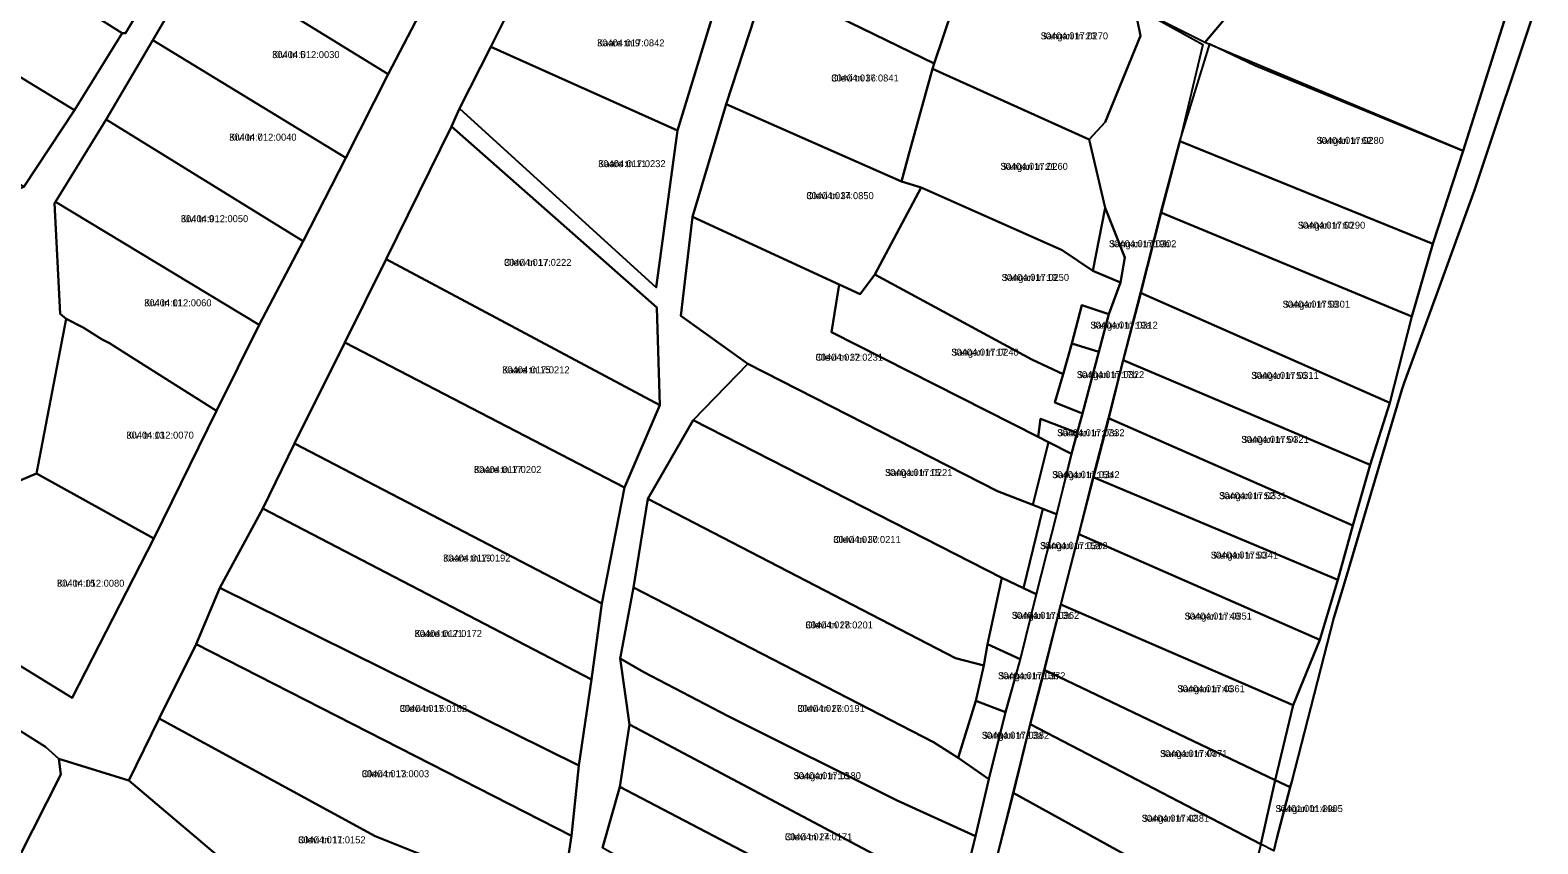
# Model space of a CAD drawing. Extents: x 542681 to 554572, y 6566489 to 6580482.
# Drawn here: x 544141.3 to 544465.9, y 6575987.4 to 6576162.5 of the extents above; entities that cross this region are included whole.
import ezdxf

# ---------------------------------------------------------------- set-up
doc = ezdxf.new("R2010")
doc.units = 0
for name, color, linetype in [('L_AADRESS', 7, 'Continuous'), ('PIIR', 7, 'Continuous'), ('TUNNUS', 7, 'Continuous')]:
    doc.layers.add(name, color=color, linetype=linetype)

msp = doc.modelspace()

# ---------------------------------------------------------------- linework, layer by layer
at = {"layer": 'PIIR'}
for points in [[(544421, 6576191.6), (544394.2, 6576159.83), (544381.29, 6576166.31), (544369.53, 6576171.4), (544386.58, 6576207.68)], [(544128.15, 6576198.87), (544130.62, 6576202.67), (544172.2, 6576179.15), (544161.88, 6576161.84), (544161.1, 6576161.82), (544120.28, 6576187.57)], [(544299.73, 6576172.96), (544295.43, 6576175.19), (544300.42, 6576176.92), (544309.48, 6576196.57), (544344.06, 6576179.43), (544335.91, 6576155.29)], [(544188.39, 6576194.26), (544189.79, 6576193.88), (544227.68, 6576170.79), (544218.42, 6576152.97), (544177.97, 6576177.9)], [(544434.83, 6576185.24), (544442.01, 6576193.33), (544442.75, 6576189.94), (544463.43, 6576179.69), (544449.82, 6576136.52), (544394.2, 6576159.83), (544421, 6576191.6)], [(544115.93, 6576181.35), (544120.28, 6576187.57), (544161.1, 6576161.82), (544150.9, 6576145.26), (544108.81, 6576170.96)], [(544344.06, 6576179.43), (544344.75, 6576182.07), (544375.81, 6576167.47), (544379.6, 6576164.76), (544380.36, 6576161.26), (544372.71, 6576142.68), (544369.28, 6576138.91), (544335.58, 6576154.14), (544335.91, 6576155.29)], [(544177.97, 6576177.9), (544218.42, 6576152.97), (544209.29, 6576135.03), (544167.75, 6576160.33)], [(544240.49, 6576158.91), (544248.48, 6576174.91), (544291.75, 6576177.06), (544280.65, 6576140.9)], [(544335.58, 6576154.14), (544330.6, 6576136.26), (544328.89, 6576129.9), (544291.15, 6576146.53), (544299.73, 6576172.96), (544335.91, 6576155.29)], [(544103.91, 6576164.12), (544108.81, 6576170.96), (544150.9, 6576145.26), (544139.99, 6576128.75), (544097.55, 6576154.68)], [(544167.75, 6576160.33), (544209.29, 6576135.03), (544200.13, 6576117.06), (544157.66, 6576143.26)], [(544388.78, 6576138.59), (544395.23, 6576159.52), (544405.01, 6576154.9), (544449.82, 6576136.52), (544443.25, 6576116.48)], [(544240.49, 6576158.91), (544280.65, 6576140.9), (544276.06, 6576107.08), (544233.74, 6576145.65)], [(544328.89, 6576129.9), (544330.6, 6576136.26), (544335.58, 6576154.14), (544369.28, 6576138.91), (544372.76, 6576124.24), (544370.08, 6576110.68), (544363.45, 6576115.13), (544333.09, 6576128.58)], [(544291.15, 6576146.53), (544328.89, 6576129.9), (544333.09, 6576128.58), (544323.16, 6576109.86), (544320.02, 6576105.69), (544315.45, 6576107.76), (544283.92, 6576122.33)], [(544157.66, 6576143.26), (544200.13, 6576117.06), (544190.66, 6576099.04), (544146.79, 6576125.53)], [(544232.03, 6576141.72), (544276.23, 6576102.8), (544276.88, 6576081.78), (544217.94, 6576113.17)], [(544384.73, 6576123.22), (544388.78, 6576138.59), (544443.25, 6576116.48), (544438.77, 6576100.88)], [(544333.09, 6576128.58), (544363.45, 6576115.13), (544370.08, 6576110.68), (544376.05, 6576108.18), (544373.54, 6576101.37), (544367.71, 6576103.28), (544365.56, 6576095.06), (544363.7, 6576088.45), (544356.92, 6576091.58), (544323.16, 6576109.86)], [(544146.54, 6576125.22), (544146.79, 6576125.53), (544190.66, 6576099.04), (544181.42, 6576080.58), (544165.84, 6576090.36), (544158.38, 6576095.09), (544156.84, 6576095.9), (544152.73, 6576098.48), (544149.06, 6576100.33), (544147.81, 6576101.4)], [(544376.99, 6576113.58), (544376.05, 6576108.18), (544370.08, 6576110.68), (544372.76, 6576124.24)], [(544281.41, 6576100.98), (544283.92, 6576122.33), (544315.45, 6576107.76), (544313.84, 6576097.48), (544358.27, 6576074.96), (544360.55, 6576073.83), (544357.13, 6576060.34), (544349.57, 6576063.23), (544295.78, 6576090.65)], [(544380.33, 6576105.93), (544384.73, 6576123.22), (544438.77, 6576100.88), (544434.03, 6576082.25)], [(544217.94, 6576113.17), (544276.88, 6576081.78), (544269.25, 6576064.08), (544209.08, 6576095.23)], [(544315.45, 6576107.76), (544320.02, 6576105.69), (544323.16, 6576109.86), (544356.92, 6576091.58), (544363.7, 6576088.45), (544361.89, 6576082.37), (544367.82, 6576079.98), (544366.71, 6576075.84), (544358.83, 6576078.86), (544358.27, 6576074.96), (544313.84, 6576097.48)], [(544376.58, 6576091.45), (544380.33, 6576105.93), (544434.03, 6576082.25), (544429.78, 6576068.92)], [(544367.71, 6576103.28), (544373.54, 6576101.37), (544371.36, 6576093.22), (544365.56, 6576095.06)], [(544149.06, 6576100.33), (544152.73, 6576098.48), (544156.84, 6576095.9), (544158.38, 6576095.09), (544165.84, 6576090.36), (544181.42, 6576080.58), (544167.98, 6576053.1), (544142.67, 6576067.09)], [(544209.08, 6576095.23), (544269.25, 6576064.08), (544264.4, 6576039.1), (544198.26, 6576073.49)], [(544363.7, 6576088.45), (544365.56, 6576095.06), (544371.36, 6576093.22), (544367.82, 6576079.98), (544361.89, 6576082.37)], [(544373.44, 6576078.94), (544376.58, 6576091.45), (544429.78, 6576068.92), (544426.05, 6576055.86)], [(544295.78, 6576090.65), (544349.57, 6576063.23), (544357.13, 6576060.34), (544359.28, 6576059.48), (544355.18, 6576042.4), (544350.48, 6576044.64), (544284.03, 6576078.54)], [(544284.03, 6576078.54), (544350.48, 6576044.64), (544347.38, 6576030.33), (544346.61, 6576025.71), (544340.53, 6576027.33), (544274.31, 6576061.6)], [(544358.27, 6576074.96), (544358.83, 6576078.86), (544366.71, 6576075.84), (544365.51, 6576071.33), (544360.55, 6576073.83)], [(544370.16, 6576066.26), (544373.44, 6576078.94), (544426.05, 6576055.86), (544422.84, 6576044.15)], [(544198.26, 6576073.49), (544264.4, 6576039.1), (544262.15, 6576022.75), (544191.4, 6576059.54)], [(544357.13, 6576060.34), (544360.55, 6576073.83), (544365.51, 6576071.33), (544362.26, 6576058.32), (544359.28, 6576059.48)], [(544136.1, 6576064.24), (544142.67, 6576067.09), (544167.98, 6576053.1), (544150.34, 6576018.8), (544126.25, 6576033.56)], [(544367.04, 6576054.02), (544370.16, 6576066.26), (544422.84, 6576044.15), (544418.91, 6576031.24)], [(544191.4, 6576059.54), (544262.15, 6576022.75), (544259.46, 6576004.22), (544182.18, 6576042.45)], [(544274.31, 6576061.6), (544340.53, 6576027.33), (544346.61, 6576025.71), (544344.9, 6576018.12), (544341.09, 6576005.84), (544335.74, 6576009.24), (544271.21, 6576042.52)], [(544355.18, 6576042.4), (544359.28, 6576059.48), (544362.26, 6576058.32), (544357.88, 6576041.11)], [(544363.16, 6576038.9), (544367.04, 6576054.02), (544418.91, 6576031.24), (544413.21, 6576017.24)], [(544259.46, 6576004.22), (544257.89, 6575989.06), (544177.07, 6576030.33), (544182.18, 6576042.45)], [(544273.43, 6576024.32), (544268.31, 6576027.25), (544271.21, 6576042.52), (544335.74, 6576009.24), (544341.09, 6576005.84), (544347.66, 6576001.27), (544344.79, 6575988.99), (544327.96, 6575996.68), (544291.56, 6576014.86)], [(544347.38, 6576030.33), (544350.48, 6576044.64), (544355.18, 6576042.4), (544357.88, 6576041.11), (544354.44, 6576027.12)], [(544359.63, 6576024.8), (544363.16, 6576038.9), (544413.21, 6576017.24), (544409.31, 6576001.08)], [(544177.07, 6576030.33), (544257.89, 6575989.06), (544255.42, 6575973.07), (544215.56, 6575989.04), (544169.12, 6576014.32)], [(544346.61, 6576025.71), (544347.38, 6576030.33), (544354.44, 6576027.12), (544351.24, 6576015.7), (544344.9, 6576018.12)], [(544268.31, 6576027.25), (544273.43, 6576024.32), (544291.56, 6576014.86), (544327.96, 6575996.68), (544344.79, 6575988.99), (544341.42, 6575975.31), (544270.37, 6576013.07)], [(544356.57, 6576013.09), (544359.63, 6576024.8), (544409.31, 6576001.08), (544406.24, 6575987.27)], [(544105.46, 6575997.25), (544116.43, 6576006.3), (544126.15, 6576019.88), (544144.61, 6576008.23), (544147.47, 6576005.67), (544147.93, 6576002.3), (544132.71, 6575972.4), (544099.16, 6575989.84)], [(544341.09, 6576005.84), (544344.9, 6576018.12), (544351.24, 6576015.7), (544347.66, 6576001.27)], [(544215.56, 6575989.04), (544255.42, 6575973.07), (544253.22, 6575960.63), (544244.77, 6575965.24), (544227.3, 6575972.12), (544210.1, 6575979.19), (544202.83, 6575966.95), (544162.57, 6576001.02), (544169.12, 6576014.32)], [(544270.37, 6576013.07), (544341.42, 6575975.31), (544337.96, 6575963.2), (544268.29, 6575999.66)], [(544352.95, 6575998.35), (544356.57, 6576013.09), (544406.24, 6575987.27), (544402.23, 6575971.12)], [(544406.24, 6575987.27), (544409.31, 6576001.08), (544412.55, 6575999.54), (544409.71, 6575988.58), (544409, 6575985.84)], [(544337.96, 6575963.2), (544337.03, 6575959.16), (544332.67, 6575961.4), (544328.86, 6575950.04), (544264.52, 6575986.52), (544268.29, 6575999.66)], [(544349.45, 6575984.68), (544352.95, 6575998.35), (544402.23, 6575971.12), (544399.2, 6575957.07)]]:
    msp.add_lwpolyline(points, close=True, dxfattribs=at)
for points in [[(544177.97, 6576177.9), (544167.75, 6576160.33), (544157.66, 6576143.26), (544146.79, 6576125.53), (544146.54, 6576125.22), (544147.81, 6576101.4), (544149.06, 6576100.33), (544142.67, 6576067.09), (544136.1, 6576064.24), (544114.41, 6576077.03), (544113.49, 6576075.86), (544093.54, 6576088.13), (544089.87, 6576091.5), (544109.84, 6576116.75), (544139.99, 6576128.75), (544150.9, 6576145.26), (544161.1, 6576161.82), (544161.88, 6576161.84), (544172.2, 6576179.15)], [(544465.86, 6576168.89), (544452.24, 6576128.05), (544443.81, 6576104.97), (544437.09, 6576086.54), (544436.56, 6576085.08), (544432.33, 6576070.85), (544429.18, 6576060.22), (544425.07, 6576046.42), (544423.78, 6576042.08), (544421.97, 6576035.98), (544417.71, 6576019.52), (544412.87, 6576000.8), (544412.55, 6575999.54), (544409.31, 6576001.08), (544413.21, 6576017.24), (544418.91, 6576031.24), (544422.84, 6576044.15), (544426.05, 6576055.86), (544429.78, 6576068.92), (544434.03, 6576082.25), (544438.77, 6576100.88), (544443.25, 6576116.48), (544449.82, 6576136.52), (544463.43, 6576179.69)], [(544132.71, 6575972.4), (544147.93, 6576002.3), (544147.47, 6576005.67), (544162.57, 6576001.02), (544202.83, 6575966.95), (544220.16, 6575955.78), (544237.67, 6575945.07), (544240.53, 6575949.86), (544248.94, 6575944.56), (544253.22, 6575960.63), (544255.42, 6575973.07), (544257.89, 6575989.06), (544259.46, 6576004.22), (544262.15, 6576022.75), (544264.4, 6576039.1), (544269.25, 6576064.08), (544276.88, 6576081.78), (544276.23, 6576102.8), (544232.03, 6576141.72), (544233.74, 6576145.65), (544276.06, 6576107.08), (544280.65, 6576140.9), (544291.75, 6576177.06)], [(544248.48, 6576174.91), (544240.49, 6576158.91), (544233.74, 6576145.65), (544232.03, 6576141.72), (544217.94, 6576113.17), (544209.08, 6576095.23), (544198.26, 6576073.49), (544191.4, 6576059.54), (544182.18, 6576042.45), (544177.07, 6576030.33), (544169.12, 6576014.32), (544162.57, 6576001.02), (544147.47, 6576005.67), (544144.61, 6576008.23), (544126.15, 6576019.88)], [(544299.73, 6576172.96), (544291.15, 6576146.53), (544283.92, 6576122.33), (544281.41, 6576100.98), (544295.78, 6576090.65), (544284.03, 6576078.54), (544274.31, 6576061.6), (544271.21, 6576042.52), (544268.31, 6576027.25), (544270.37, 6576013.07), (544268.29, 6575999.66), (544264.52, 6575986.52)], [(544126.25, 6576033.56), (544150.34, 6576018.8), (544167.98, 6576053.1), (544181.42, 6576080.58), (544190.66, 6576099.04), (544200.13, 6576117.06), (544209.29, 6576135.03), (544218.42, 6576152.97), (544227.68, 6576170.79)], [(544409, 6575985.84), (544409.71, 6575988.58), (544412.55, 6575999.54), (544412.87, 6576000.8), (544417.71, 6576019.52), (544421.97, 6576035.98), (544423.78, 6576042.08), (544425.07, 6576046.42), (544429.18, 6576060.22), (544432.33, 6576070.85), (544436.56, 6576085.08), (544437.09, 6576086.54), (544443.81, 6576104.97), (544452.24, 6576128.05), (544465.86, 6576168.89)], [(544381.29, 6576166.31), (544393.77, 6576159.4), (544388.82, 6576138.6), (544384.78, 6576123.23), (544380.38, 6576105.94), (544376.63, 6576091.46), (544373.49, 6576078.95), (544370.21, 6576066.27), (544367.09, 6576054.03), (544363.21, 6576038.91), (544359.68, 6576024.81), (544356.57, 6576013.09), (544353, 6575998.36), (544349.5, 6575984.69), (544346.24, 6575972.34), (544343.11, 6575959.91), (544339.38, 6575944.78), (544335.04, 6575928.31), (544331.32, 6575913.02), (544326.6, 6575895.05), (544322.67, 6575879.05), (544318.89, 6575865.14), (544314.59, 6575849.07), (544309.48, 6575828.97)], [(544341.42, 6575975.31), (544344.79, 6575988.99), (544347.66, 6576001.27), (544351.24, 6576015.7), (544354.49, 6576027.13), (544357.93, 6576041.12), (544362.31, 6576058.33), (544365.51, 6576071.33), (544366.71, 6576075.84), (544367.82, 6576079.98), (544371.36, 6576093.22), (544373.54, 6576101.37), (544376.05, 6576108.18), (544376.99, 6576113.58), (544372.76, 6576124.24), (544369.28, 6576138.91), (544372.71, 6576142.68), (544380.36, 6576161.26), (544379.6, 6576164.76)]]:
    msp.add_lwpolyline(points, dxfattribs=at)

# ---------------------------------------------------------------- texts
at = {"layer": 'L_AADRESS'}
for s, p in [('Kaare tn 9', (544263.36, 6576158.98)), ('Sangari tn 23', (544358.85, 6576160.49)), ('Kivi tn 5', (544193.42, 6576156.46)), ('Olevi tn 36', (544313.78, 6576151.43)), ('Kivi tn 7', (544184.17, 6576138.69)), ('Sangari tn 62', (544418.22, 6576138)), ('Kaare tn 11', (544263.6, 6576132.99)), ('Sangari tn 21', (544350.19, 6576132.41)), ('Olevi tn 34', (544308.41, 6576126.11)), ('Kivi tn 9', (544173.77, 6576121.15)), ('Sangari tn 60', (544414.2, 6576119.74)), ('Sangari tn 19b', (544373.54, 6576115.76)), ('Olevi tn 17', (544243.34, 6576111.75)), ('Sangari tn 19', (544350.45, 6576108.51)), ('Kivi tn 11', (544165.87, 6576103.05)), ('Sangari tn 58', (544410.93, 6576102.74)), ('Sangari tn 19a', (544369.55, 6576098.24)), ('Olevi tn 32', (544310.4, 6576091.33)), ('Sangari tn 17', (544339.61, 6576092.41)), ('Kaare tn 15', (544242.93, 6576088.62)), ('Sangari tn 17b', (544366.62, 6576087.59)), ('Sangari tn 56', (544404.19, 6576087.43)), ('Kivi tn 13', (544162.05, 6576074.57)), ('Sangari tn 17a', (544362.4, 6576075.09)), ('Sangari tn 54', (544402.04, 6576073.65)), ('Kaare tn 17', (544236.86, 6576067.17)), ('Sangari tn 15', (544325.34, 6576066.52)), ('Sangari tn 15b', (544361.32, 6576066.06)), ('Sangari tn 52', (544397.24, 6576061.54)), ('Olevi tn 30', (544314.21, 6576052.12)), ('Sangari tn 15a', (544358.72, 6576050.78)), ('Kaare tn 19', (544230.21, 6576048.12)), ('Sangari tn 50', (544395.46, 6576048.75)), ('Kivi tn 15', (544147.11, 6576042.7)), ('Sangari tn 13c', (544352.63, 6576035.78)), ('Sangari tn 48', (544389.82, 6576035.63)), ('Kaare tn 21', (544224.07, 6576031.88)), ('Olevi tn 28', (544308.23, 6576033.72)), ('Sangari tn 13b', (544349.67, 6576022.79)), ('Sangari tn 46', (544388.28, 6576019.99)), ('Olevi tn 15', (544220.88, 6576015.75)), ('Olevi tn 26', (544306.48, 6576015.75)), ('Sangari tn 13a', (544346.17, 6576009.97)), ('Sangari tn 44', (544384.54, 6576006.04)), ('Olevi tn 13', (544212.72, 6576001.7)), ('Sangari tn 13', (544305.65, 6576001.28)), ('Sangari tn 42', (544380.6, 6575992.11)), ('Sangari tn 44a', (544409.39, 6575994.2)), ('Olevi tn 11', (544199.02, 6575987.48)), ('Olevi tn 24', (544303.8, 6575988.13))]:
    msp.add_text(s, height=1.5, dxfattribs=at).set_placement(p)
at = {"layer": 'TUNNUS'}
for s, p in [('30404:017:0842', (544263.36, 6576158.98)), ('30404:017:0270', (544358.85, 6576160.49)), ('30404:012:0030', (544193.42, 6576156.46)), ('30404:017:0841', (544313.78, 6576151.43)), ('30404:012:0040', (544184.17, 6576138.69)), ('30404:017:0280', (544418.22, 6576138)), ('30404:017:0232', (544263.6, 6576132.99)), ('30404:017:0260', (544350.19, 6576132.41)), ('30404:017:0850', (544308.41, 6576126.11)), ('30404:012:0050', (544173.77, 6576121.15)), ('30404:017:0290', (544414.2, 6576119.74)), ('30404:017:0302', (544373.54, 6576115.76)), ('30404:017:0222', (544243.34, 6576111.75)), ('30404:017:0250', (544350.45, 6576108.51)), ('30404:012:0060', (544165.87, 6576103.05)), ('30404:017:0301', (544410.93, 6576102.74)), ('30404:017:0312', (544369.55, 6576098.24)), ('30404:017:0231', (544310.4, 6576091.33)), ('30404:017:0240', (544339.61, 6576092.41)), ('30404:017:0212', (544242.93, 6576088.62)), ('30404:017:0322', (544366.62, 6576087.59)), ('30404:017:0311', (544404.19, 6576087.43)), ('30404:012:0070', (544162.05, 6576074.57)), ('30404:017:0332', (544362.4, 6576075.09)), ('30404:017:0321', (544402.04, 6576073.65)), ('30404:017:0202', (544236.86, 6576067.17)), ('30404:017:0221', (544325.34, 6576066.52)), ('30404:017:0342', (544361.32, 6576066.06)), ('30404:017:0331', (544397.24, 6576061.54)), ('30404:017:0211', (544314.21, 6576052.12)), ('30404:017:0352', (544358.72, 6576050.78)), ('30404:017:0192', (544230.21, 6576048.12)), ('30404:017:0341', (544395.46, 6576048.75)), ('30404:012:0080', (544147.11, 6576042.7)), ('30404:017:0362', (544352.63, 6576035.78)), ('30404:017:0351', (544389.82, 6576035.63)), ('30404:017:0172', (544224.07, 6576031.88)), ('30404:017:0201', (544308.23, 6576033.72)), ('30404:017:0372', (544349.67, 6576022.79)), ('30404:017:0361', (544388.28, 6576019.99)), ('30404:017:0162', (544220.88, 6576015.75)), ('30404:017:0191', (544306.48, 6576015.75)), ('30404:017:0382', (544346.17, 6576009.97)), ('30404:017:0371', (544384.54, 6576006.04)), ('30404:017:0003', (544212.72, 6576001.7)), ('30404:017:0180', (544305.65, 6576001.28)), ('30404:017:0381', (544380.6, 6575992.11)), ('30401:001:2905', (544409.39, 6575994.2)), ('30404:017:0152', (544199.02, 6575987.48)), ('30404:017:0171', (544303.8, 6575988.13))]:
    msp.add_text(s, height=1.5, dxfattribs=at).set_placement(p)

doc.saveas('drawing.dxf')
